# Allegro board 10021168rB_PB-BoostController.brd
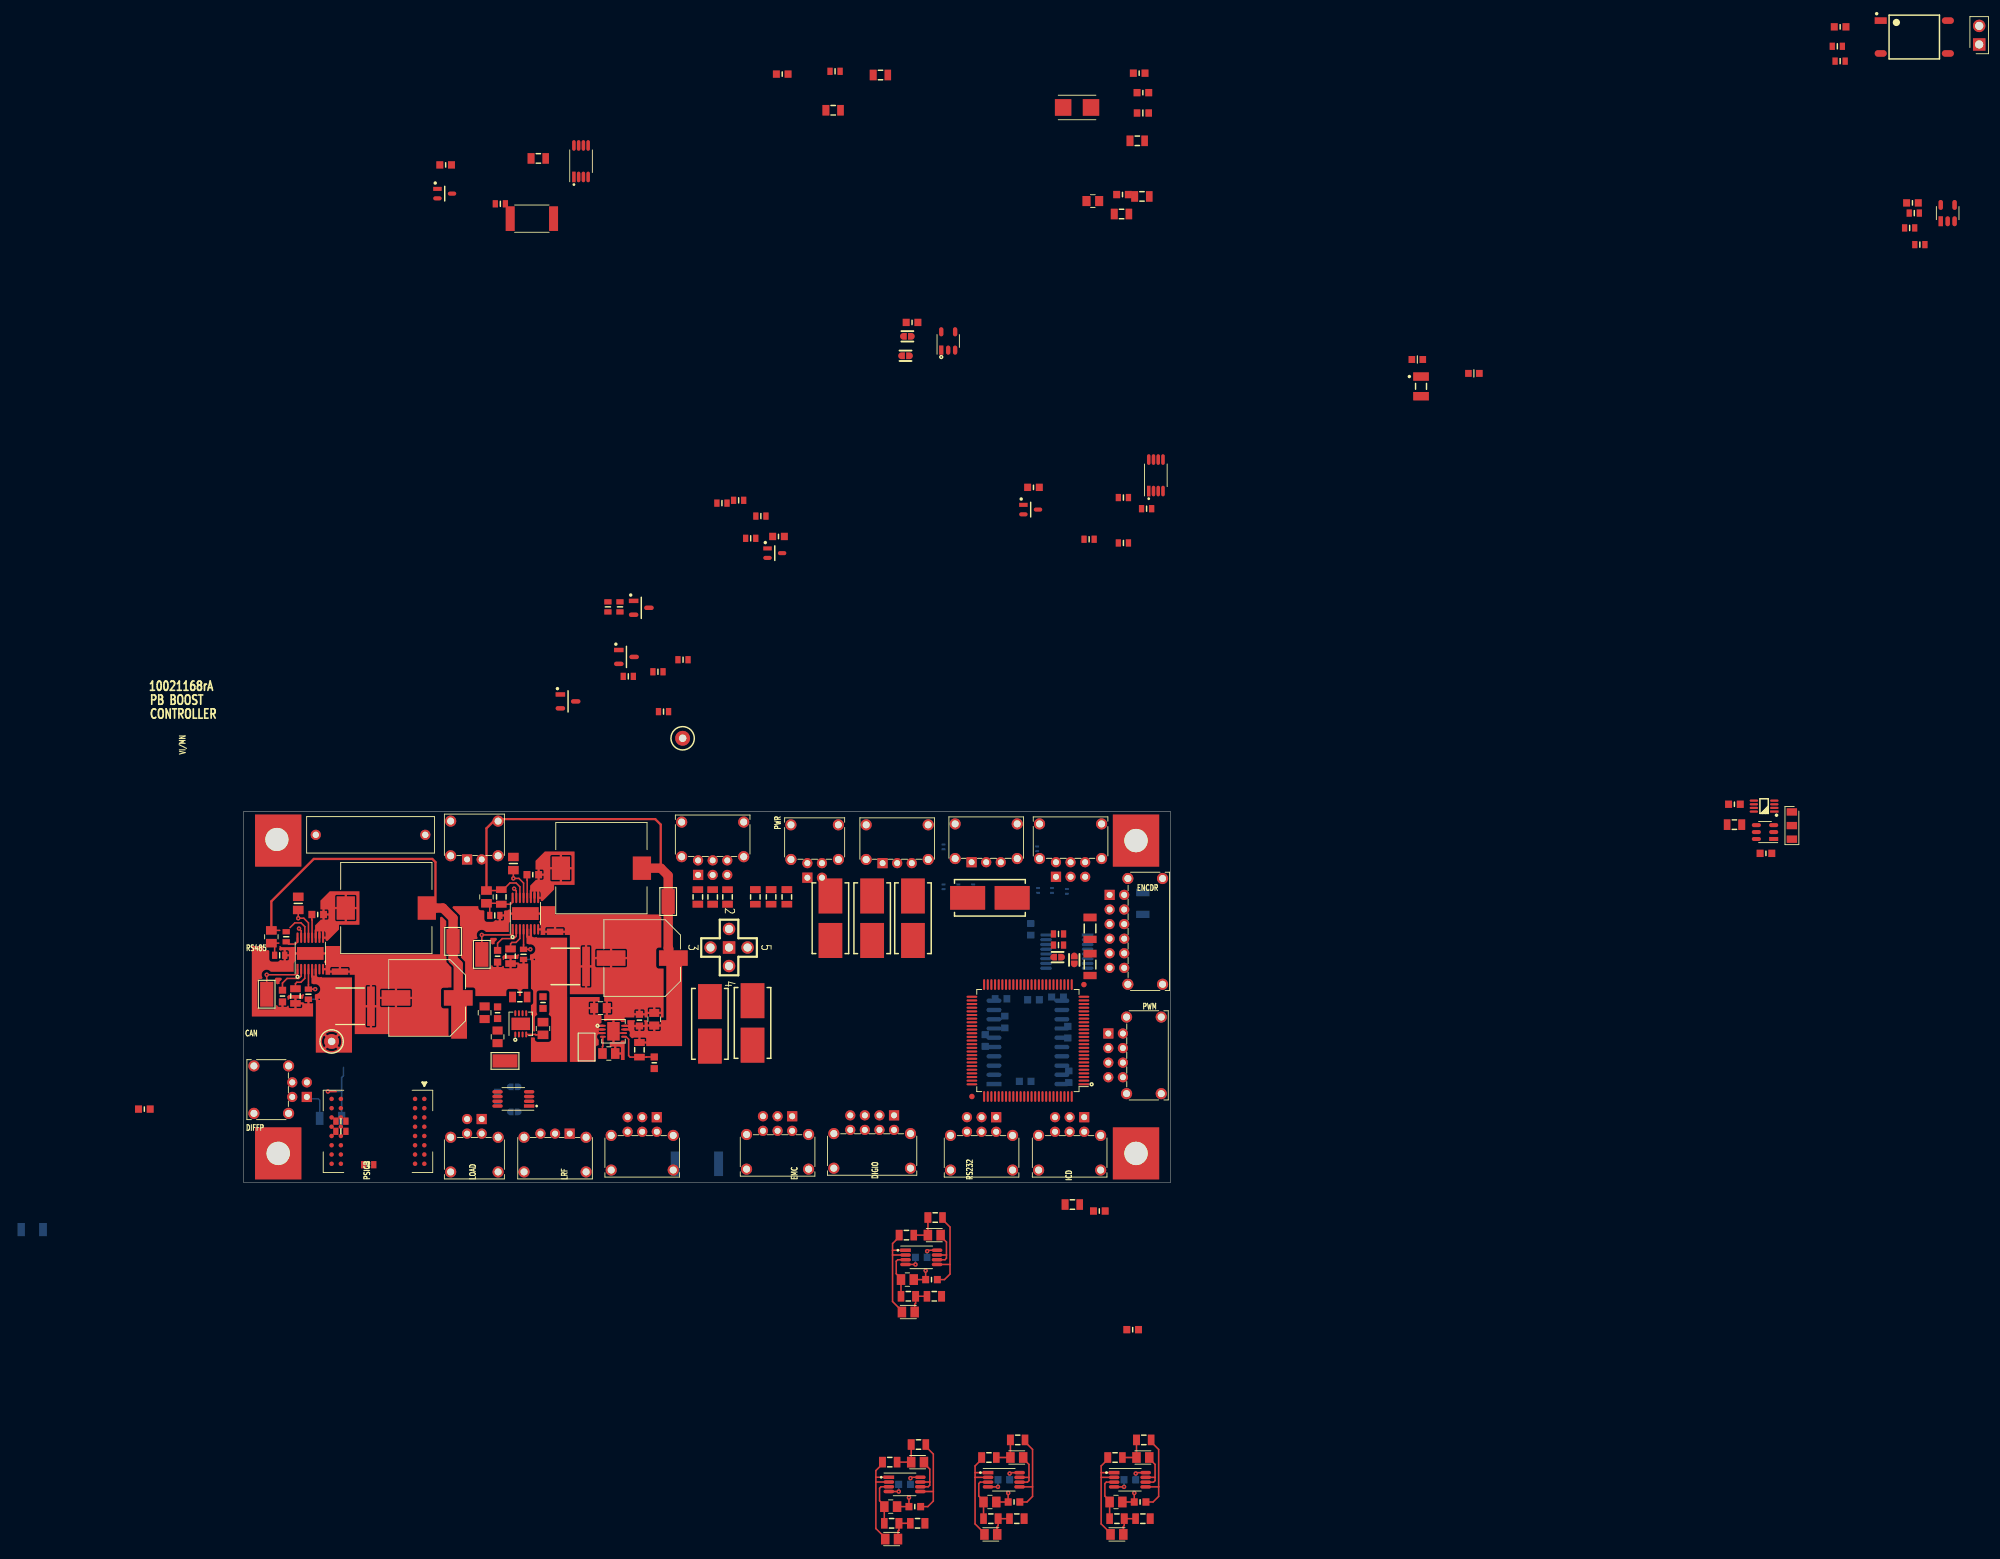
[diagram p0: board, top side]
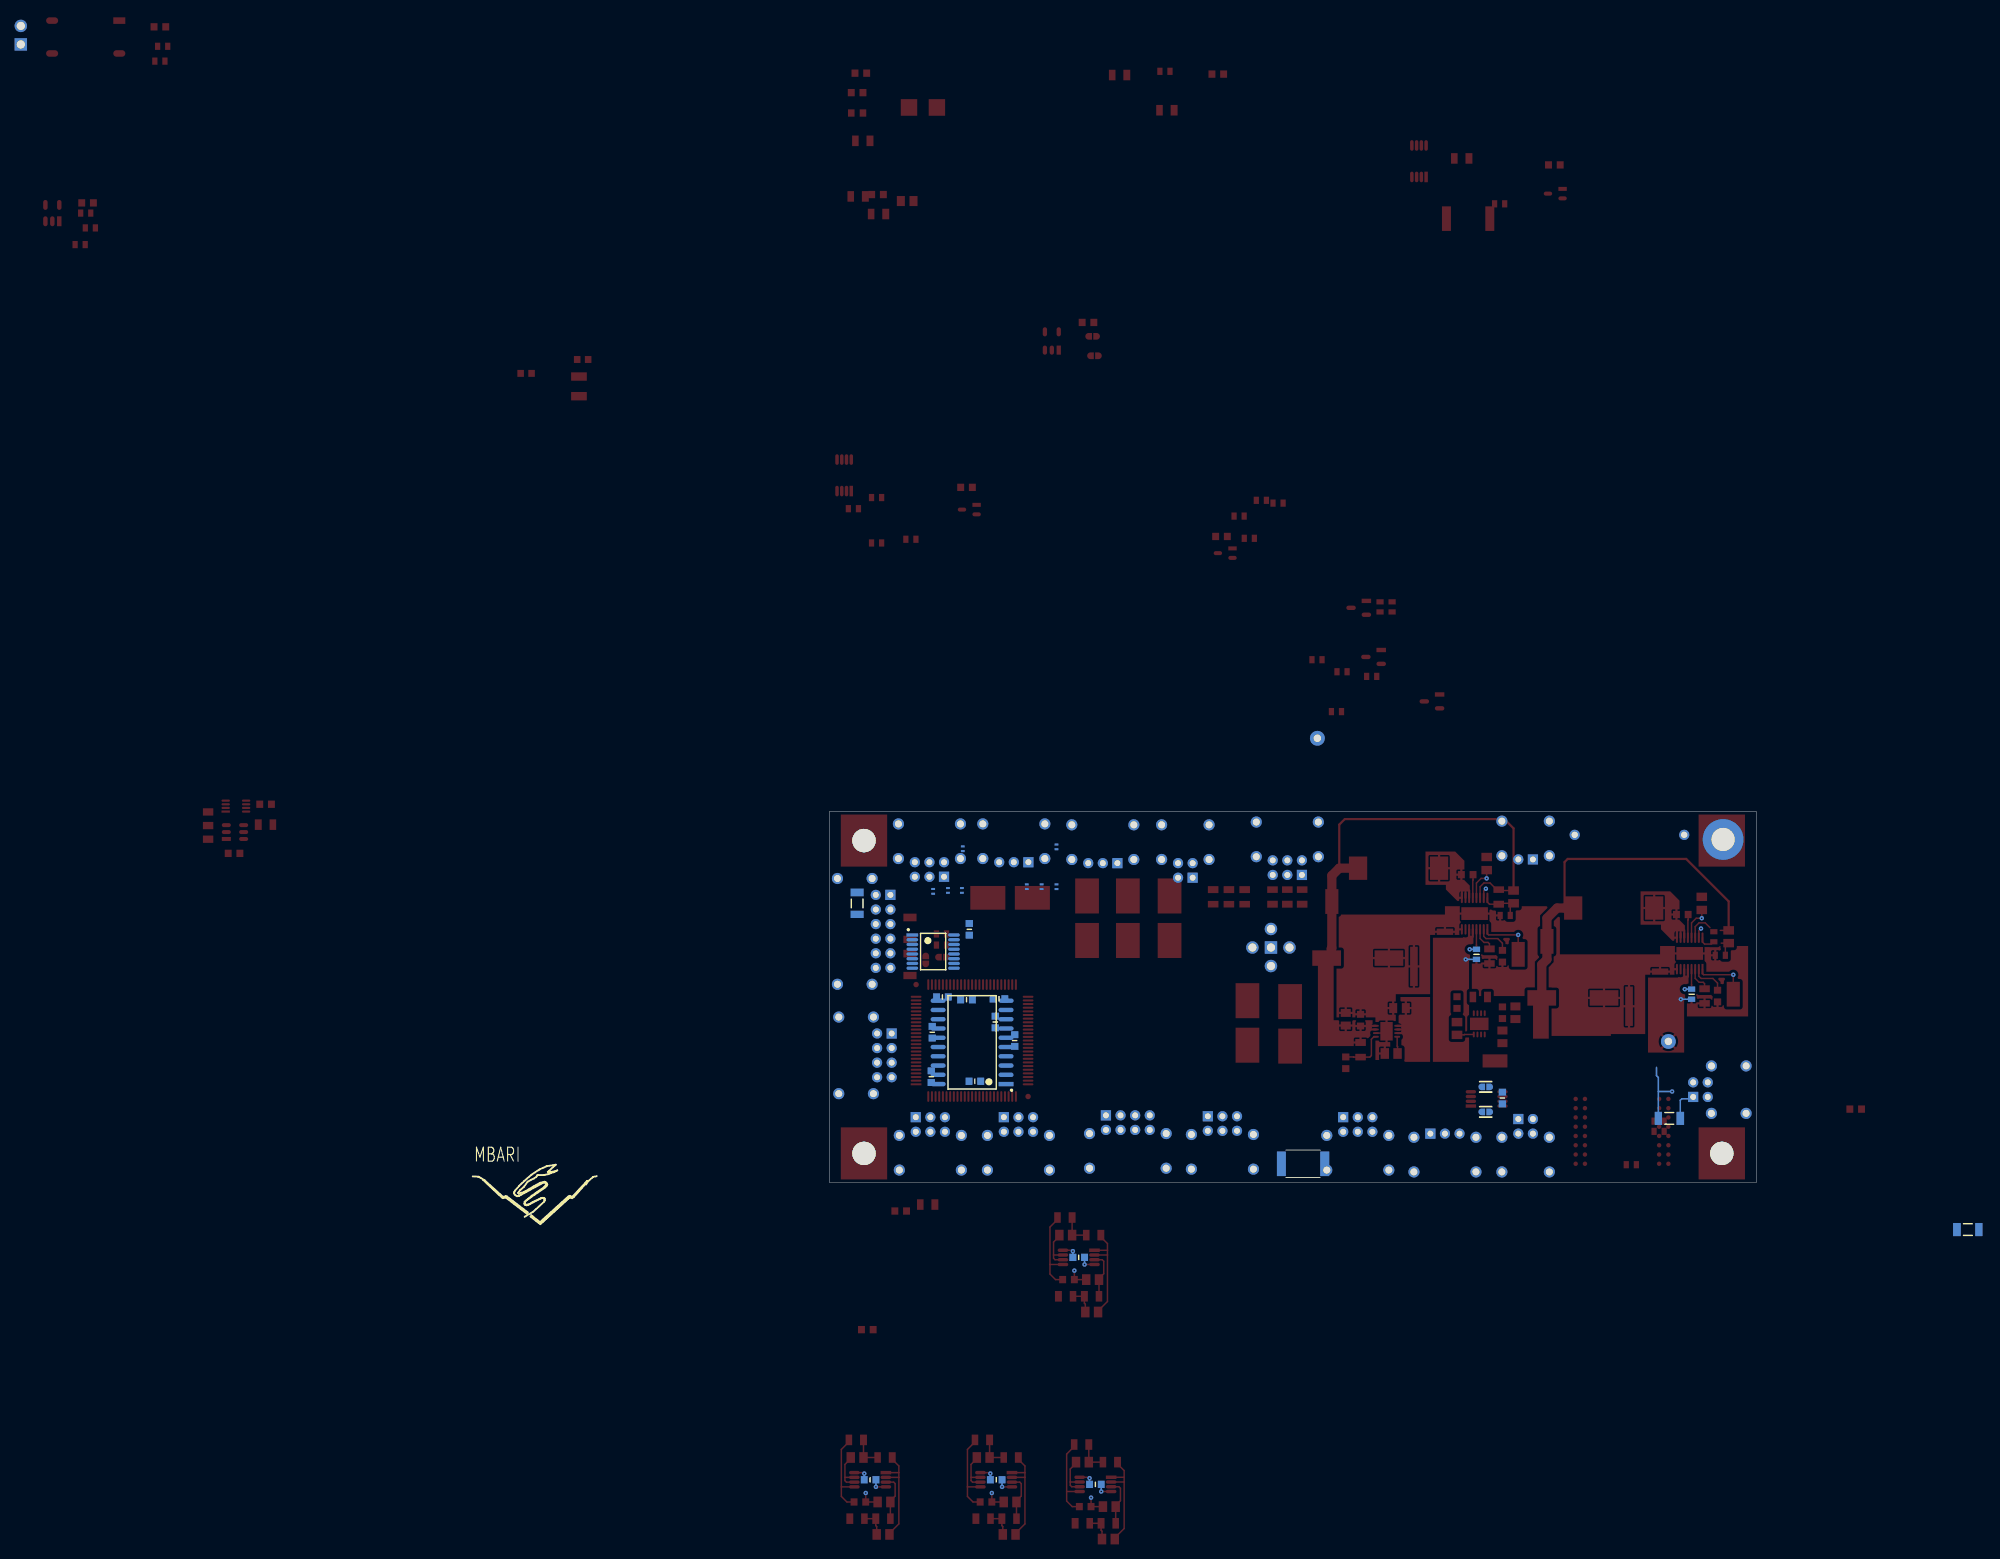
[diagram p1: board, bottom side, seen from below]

Outline 127 x 50.8 mm; copper layers: TOP, GND1, PWR, INR1, GND2, BOTTOM. Coordinates in mm from the lower left corner of the outline.
Outline path: 0,50.8 0,0 127,0 127,50.8 0,50.8

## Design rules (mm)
constraint set DEFAULT: min track width 0.203

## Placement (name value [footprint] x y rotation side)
C1  10uF  [CAPC2012X135N]  116.33 134.49 0 top
C2  0.10uF  [CAPC1608X87N]  120.4 135.38 0 top
C3  0.10uF  [CAPC1608X87N]  218.69 158.37 0 top
C4  22pF  [CAPC1608X90N_G100]  160.78 112.78 0 top
C5  22pF  [CAPC1608X90N_G100]  168.53 110.87 0 top
C6  33pF  [CAPC1608X90N]  122.68 152.02 0 top
C7  33pF  [CAPC1608X90N]  123.19 149.35 0 top
C8  0.10uF  [CAPC1608X87N]  103.76 25.15 180 bottom
C9  0.10uF  [CAPC1608X87N]  108.2 25.02 180 bottom
C10  0.10uF  [CAPC1608X87N]  111.51 25.4 180 bottom
C11  0.10uF  [CAPC1608X87N]  112.9 20.57 270 bottom
C12  0.10uF  [CAPC1608X87N]  113.03 14.48 270 bottom
C13  0.10uF  [CAPC1608X87N]  107.06 13.84 0 bottom
C14  0.10uF  [CAPC1608X87N]  101.6 19.43 270 bottom
C15  0.10uF  [CAPC1608X87N]  104.27 21.97 90 bottom
C39  0.10uF  [CAPC1608X87N]  117.22 -3.94 0 top
C40  0.10uF  [CAPC1608X87N]  34.8 11.56 90 bottom
C41  0.10uF  [CAPC1608X87N]  121.79 -20.19 0 top
C43  680pF  [CAPC2012X88N]  90.93 -13.34 0 top
C44  560pF  [CAPC1608X90N]  94.23 -13.34 180 top
C45  6800pF  [CAPC2012X90N]  91.06 -17.78 180 top
C46  6800pF  [CAPC2012X90N]  94.61 -7.24 0 top
C47  0.10uF  [CAPC1608X87N]  92.84 -10.29 180 bottom
C51  680pF  [CAPC2012X88N]  119.51 -43.81 0 top
C52  560pF  [CAPC1608X90N]  122.81 -43.81 180 top
C54  6800pF  [CAPC2012X90N]  119.63 -48.26 180 top
C55  6800pF  [CAPC2012X90N]  123.19 -37.72 0 top
C56  0.10uF  [CAPC1608X87N]  121.41 -40.77 180 bottom
C60  680pF  [CAPC2012X88N]  102.23 -43.81 0 top
C61  560pF  [CAPC1608X90N]  105.54 -43.81 180 top
C63  6800pF  [CAPC2012X90N]  102.36 -48.26 180 top
C64  6800pF  [CAPC2012X90N]  105.92 -37.72 0 top
C65  0.10uF  [CAPC1608X87N]  104.14 -40.77 180 bottom
C69  680pF  [CAPC2012X88N]  88.65 -44.45 0 top
C70  560pF  [CAPC1608X90N]  91.95 -44.45 180 top
C72  6800pF  [CAPC2012X90N]  88.77 -48.9 180 top
C73  6800pF  [CAPC2012X90N]  92.33 -38.35 0 top
C74  0.10uF  [CAPC1608X87N]  90.55 -41.4 180 bottom
C76  0.10uF  [CAPC1608X87N]  73.28 88.52 0 top
C77  0.10uF  [CAPC1608X87N]  108.2 95.25 0 top
C78  0.10uF  [CAPC1608X87N]  27.69 139.45 0 top
C79  0.10uF  [CAPC1608X87N]  73.79 151.89 0 top
C87  0.10uF  [CAPC1608X87N]  107.82 34.67 90 bottom
C88  0.10uF  [CAPC1608X87N]  228.6 134.24 0 top
C89  0.10uF  [CAPC1608X87N]  91.57 117.86 0 top
C90  0.10uF  [CAPC1608X87N]  -13.59 10.03 0 top
C91  BFC233860103  [CAPRR1500W60L1750T500H1100B]  17.4 47.62 0 top
C92  10.0pF  [CAPC2012X88N]  33.27 39.12 90 top
C93  1.0uF  [CAPC2012X140N]  36.96 43.69 90 top
C94  0.10uF  [CAPC1608X87N]  39.62 42.16 0 top
C95  0.10uF  [CAPC1608X87N]  34.8 30.99 270 top
C96  10uF  [CAPC5750X250N]  44.07 29.59 0 top
C97  0.10uF  [CAPC127X200X102L23N]  42.67 33.66 90 top
C98  10uF  [CAPC2012X135N]  56.26 22.35 90 top
C99  0.10uF  [CAPC1608X87N]  54.23 22.23 90 top
C100  2200uF  [CAPAE1030X1380DD450L320N]  54.61 30.73 180 top
C101  10uF  [CAPC2012X135N]  48.9 23.88 0 top
C102  0.10uF  [CAPC1608X87N]  56.26 16.38 270 top
C103  1000.0pF  [CAPC2012X88N]  50.04 17.65 0 top
C104  0.10uF  [CAPC1608X87N]  208.53 45.09 0 top
C105  0.10uF  [CAPC1608X87N]  204.22 51.82 180 top
C106  10.0pF  [CAPC2012X88N]  3.81 33.66 90 top
C107  1.0uF  [CAPC2012X140N]  7.49 38.23 90 top
C108  0.10uF  [CAPC1608X87N]  10.16 36.7 0 top
C109  0.10uF  [CAPC1608X87N]  5.33 25.53 270 top
C110  10uF  [CAPC5750X250N]  14.61 24.13 0 top
C111  0.10uF  [CAPC127X200X102L23N]  13.21 28.19 90 top
C112  10uF  [CAPC2012X135N]  33.02 23.24 270 top
C113  0.10uF  [CAPC1608X87N]  34.8 23.24 270 top
C114  2200uF  [CAPAE1030X1380DD450L320N]  25.15 25.27 180 top
C115  10uF  [CAPC2012X135N]  34.8 19.94 90 top
C116  0.10uF  [CAPC1608X87N]  41.02 24.64 270 top
C117  1000.0pF  [CAPC2012X88N]  41.02 21.08 90 top
D3  RCLAMP0531TQTCT  [DIONDFN2_100X60X43L25X50N]  108.84 40.01 90 bottom
D4  RCLAMP0531TQTCT  [DIONDFN2_100X60X43L25X50N]  110.74 40.01 90 bottom
D5  RCLAMP0531TQTCT  [DIONDFN2_100X60X43L25X50N]  112.78 39.88 90 bottom
D6  RCLAMP0531TQTCT  [DIONDFN2_100X60X43L25X50N]  108.71 45.72 270 bottom
D7  RCLAMP0531TQTCT  [DIONDFN2_100X60X43L25X50N]  95.89 40.51 90 bottom
D8  RCLAMP0531TQTCT  [DIONDFN2_100X60X43L25X50N]  97.92 40.51 90 bottom
D9  RCLAMP0531TQTCT  [DIONDFN2_100X60X43L25X50N]  99.95 40.51 90 bottom
D10  RCLAMP0531TQTCT  [DIONDFN2_100X60X43L25X50N]  95.89 45.97 270 bottom
DN1  BAT54SWT1G  [SOT65P220X100-3N_132]  27.56 135.51 0 top
DN9  BAT54SWT1G  [SOT65P220X100-3N_132]  107.82 92.2 0 top
DN10  BAT54SWT1G  [SOT65P220X100-3N_132]  72.77 86.23 0 top
F1  0154.125DR  [FUSM9750X381N]  91.69 36.2 270 top
F2  0154.125DR  [FUSM9750X381N]  86.11 36.2 270 top
F3  0154.125DR  [FUSM9750X381N]  80.39 36.2 270 top
F4  0154.125DR  [FUSM9750X381N]  69.72 21.84 90 top
F5  0154.125DR  [FUSM9750X381N]  102.23 38.99 180 top
F6  0154.125DR  [FUSM9750X381N]  63.88 21.72 90 top
J1  M80-8420242  [HARWIN_M80-8420242]  31.62 47.62 180 top
J2  M80-8510442  [HARWIN_M80-8510442]  3.3 12.7 270 top
J3  M80-8510642  [HARWIN_M80-8510642]  101.09 3.56 0 top
J4  M80-8510442  [HARWIN_M80-8510442]  31.62 3.3 0 top
J5  M80-8510642  [HARWIN_M80-8510642]  113.16 3.56 0 top
J6  M80-8510842  [HARWIN_M80-8510842]  86.11 3.81 0 top
J7  M80-8420342  [HARWIN_M80-8420342]  101.73 47.24 180 top
J8  M80-8420342  [HARWIN_M80-8420342]  89.53 47.12 180 top
J9  M80-8510442  [HARWIN_M80-8510442]  78.23 47.12 180 top
J10  M80-8510642  [HARWIN_M80-8510642]  54.61 3.56 0 top
J11  M80-8511242  [HARWIN_M80-8511242]  124 34.39 90 top
J12  M80-8510842  [HARWIN_M80-8510842]  123.83 17.4 90 top
J13  M80-8420342  [HARWIN_M80-8420342]  42.67 3.3 0 top
J14  M80-8510642  [HARWIN_M80-8510642]  64.26 47.5 180 top
J15  M80-8510642  [HARWIN_M80-8510642]  113.28 47.24 180 top
J16  M80-8510642  [HARWIN_M80-8510642]  73.15 3.68 0 top
JP1  LS=0.100"  [HDRV2W64P254_2X1_508X254H1363B]  237.74 155.96 90 top
JP2  QUAD JUMPER  [MISC_JMPR-SELECT-QUAD]  66.5 32.18 270 top
JR4  Low  [MISC_0805-3P-JMPR]  212.09 48.9 270 top
L3  220uH  [IND_NS-12]  49.02 43.05 0 top
L4  220uH  [IND_NS-12]  19.56 37.59 0 top
NOREF  -  []  0 0 90 top
NOREF#2  -  [unnamed#2]  122.25 3.96 0 top
NOREF#3  -  []  256.03 33.78 0 top
NOREF#4  -  []  0 0 0 top
NOREF#5  -  []  127 0 90 top
NOREF#6  -  [unnamed#2]  4.75 3.96 0 top
NOREF#7  -  []  0 0 0 top
NOREF#8  -  [unnamed#2]  122.25 46.84 0 top
NOREF#9  -  []  -50.8 -76.2 0 top
NOREF#10  -  []  0 0 0 top
NOREF#11  -  []  166.62 3.43 180 bottom
Q3  SI2308DS-T1-E3  [SOT95P237X112-3N_132]  44.45 65.91 0 top
Q4  SI2308DS-T1-E3  [SOT95P237X112-3N_132]  54.48 78.74 0 top
Q5  SI2308DS-T1-E3  [SOT95P237X112-3N_132]  52.45 72.01 0 top
R1  TBD  [RESC2012X50N]  123.06 135.13 0 top
R2  0.0  [RESC2012X50N]  120.27 132.72 0 top
R3  4.70K  [RESC1608X50N]  218.31 155.7 0 top
R4  1.00K  [RESC1608X50N]  218.69 153.67 0 top
R5  0.0  [RESC1609X55N]  123.19 146.56 0 top
R6  1.00M  [RESC2012X50N]  122.43 142.75 0 top
R24  100  [RESC2012X50N]  113.54 -3.05 0 top
R26  5.62K  [RESC2012X50N]  94.61 -15.62 180 top
R27  160.0K  [RESC2012X50N]  91.06 -15.62 180 top
R28  33.2K  [RESC2012X50N]  90.81 -7.24 0 top
R29  33.2K  [RESC2012X50N]  94.74 -4.83 0 top
R32  5.62K  [RESC2012X50N]  123.19 -46.1 180 top
R33  160.0K  [RESC2012X50N]  119.63 -46.1 180 top
R34  33.2K  [RESC2012X50N]  119.38 -37.72 0 top
R35  33.2K  [RESC2012X50N]  123.32 -35.31 0 top
R39  5.62K  [RESC2012X50N]  105.92 -46.1 180 top
R40  160.0K  [RESC2012X50N]  102.36 -46.1 180 top
R41  33.2K  [RESC2012X50N]  102.11 -37.72 0 top
R42  33.2K  [RESC2012X50N]  106.05 -35.31 0 top
R46  5.62K  [RESC2012X50N]  92.33 -46.74 180 top
R47  160.0K  [RESC2012X50N]  88.77 -46.74 180 top
R48  33.2K  [RESC2012X50N]  88.52 -38.35 0 top
R49  33.2K  [RESC2012X50N]  92.46 -35.94 0 top
R51  10.0K  [RESC1608X50N]  65.53 93.09 0 top
R52  16.2K  [RESC1608X50N]  67.82 93.47 0 top
R53  4.53K  [RESC1608X50N]  70.87 91.31 0 top
R54  10.0K  [RESC1608X50N]  115.82 88.14 0 top
R55  16.2K  [RESC1608X50N]  120.52 93.85 0 top
R56  4.53K  [RESC1608X50N]  120.52 87.63 0 top
R57  16.2K  [RESC1608X50N]  35.18 134.11 0 top
R58  150  [RESC6332X70N]  39.5 132.08 0 top
R59  0.0  [RESC2012X50N]  40.39 140.34 0 top
R60  16.2K  [RESC1608X50N]  81.03 152.27 0 top
R61  0.0  [RESC2012X50N]  80.77 146.94 0 top
R62  150  [RESC6332X70N]  62.1 2.54 180 bottom
R89  0.0  [RESC2012X50N]  87.25 151.76 0 top
R91  14.0K  [RESC1608X50N]  228.85 132.84 0 top
R92  14.0K  [RESC1608X50N]  228.22 130.81 0 top
R93  14.0K  [RESC1608X50N]  229.62 128.52 0 top
R94  60.4  [RESC3216X60N]  11.94 8.76 0 bottom
R95  60.4  [RESC3216X60N]  -28.96 -6.48 180 bottom
R96  0.0  [RESC1608X50N]  13.34 8.38 180 top
R97  TBD  [RESC1608X50N]  13.34 6.99 0 top
R98  TBD  [RESC1608X50N]  17.14 2.41 0 top
R99  TBD  [RESC1608X50N]  69.47 88.27 0 top
R100  TBD  [RESC1608X50N]  123.7 92.33 0 top
R101  165.0K  [RESC1608X50N]  52.7 69.34 0 top
R102  165.0K  [RESC1608X50N]  51.56 78.87 270 top
R103  165.0K  [RESC1608X50N]  56.77 69.98 0 top
R107  TBD  [RESC3216X60N]  115.95 34.8 270 top
R108  TBD  [RESC3216X60N]  115.95 29.84 270 top
R109  TBD  [RESC3216X60N]  123.19 38.23 270 bottom
R111  100  [RESC1608X50N]  57.53 64.52 0 top
R112  100  [RESC1608X50N]  49.91 78.87 270 top
R113  100  [RESC1608X50N]  60.2 71.63 0 top
R114  TBD  [RESC2012X50N]  62.23 39.12 90 top
R115  TBD  [RESC2012X50N]  64.26 39.12 90 top
R116  TBD  [RESC2012X50N]  66.29 39.12 90 top
R117  TBD  [RESC2012X50N]  74.42 39.12 270 top
R118  TBD  [RESC2012X50N]  72.26 39.12 270 top
R119  TBD  [RESC2012X50N]  70.1 39.12 270 top
R120  10.0K  [RESC1608X50N]  111.63 32.51 0 top
R121  10.0K  [RESC1608X50N]  111.63 34.04 0 top
R122  620.0K  [RESC2012X50N]  35.31 39.12 90 top
R123  243.0K  [RESC1608X50N]  34.42 36.58 0 top
R124  232.0K  [RESC2012X50N]  36.58 30.99 270 top
R125  20.0K  [RESC2012X50N]  54.23 18.16 270 top
R126  309.0K  [RESC1608X50N]  38.35 31.24 90 bottom
R127  619.0K  [RESC1608X50N]  38.35 31.24 270 top
R128  249.0K  [RESC2012X50N]  204.22 49.02 180 top
R129  866.0K  [RESC1608X50N]  5.84 33.66 90 top
R130  200.0K  [RESC1608X50N]  4.95 31.11 0 top
R131  232.0K  [RESC2012X50N]  7.11 25.53 270 top
R132  20.0K  [RESC2012X50N]  37.85 25.4 0 top
R133  309.0K  [RESC1608X50N]  8.89 25.78 90 bottom
R134  619.0K  [RESC1608X50N]  8.89 25.78 270 top
SB1  0603  [MISC_JUMPER_SM0603]  37.08 9.65 0 bottom
SB2  0603  [MISC_JUMPER_SM0603]  37.08 13.08 0 bottom
SB3  0603  [MISC_JUMPER_SM0603]  90.93 115.95 0 top
SB4  0603  [MISC_JUMPER_SM0603]  90.68 113.28 0 top
SB5  0603  [MISC_JUMPER_SM0603]  111.51 30.86 180 top
SB6  0603  [MISC_JUMPER_SM0603]  113.79 30.48 90 top
ST1  #4 SCREW TERMINAL  [MNT_C220H125]  4.57 46.99 0 top
SW1  FSM2JSMA  [SOIC450P1000X459R-4N]  228.85 156.97 0 top
TP1  RED  [TP_KEYSTONE_5000S_MINI]  12.06 19.3 270 top
TP2  BLACK  [TP_KEYSTONE_5000S_MINI]  60.15 60.86 0 top
TP5  5015  [TP_5015]  32.64 31.24 90 top
TP6  5015  [TP_5015]  58.17 38.48 270 top
TP7  5015  [TP_5015]  46.99 18.54 270 top
TP8  5015  [TP_5015]  3.17 25.78 90 top
TP9  5015  [TP_5015]  28.7 33.02 270 top
TP10  5015  [TP_5015]  35.81 16.64 0 top
U1  DSPIC33FJ256MC710A-H/PF  [QFP50P1600X1600X120-100L30N]  107.44 19.43 90 top
U2  REF1933AIDDCT  [SOT95P280X110-5L30N]  96.52 115.32 0 top
U8  AM26LS32ACPWR  [SOP65P640X120-16N]  112.78 31.62 180 bottom
U9  MAX3233EEWP+G36  [SOIC127P1032X265-20N]  107.44 19.18 0 bottom
U10  MAX3471EUA+  [SOP65P490X110-8L25N]  36.96 11.43 90 top
U11  24FC64FT-I/OT  [SOT23-5P95_270X145L35X35N]  233.43 132.84 0 top
U12  LTC2055HVHMS8#PBF  [SOP65P490X110-8L30N]  92.84 -10.29 270 top
U14  LTC2055HVHMS8#PBF  [SOP65P490X110-8L30N]  121.41 -40.77 270 top
U16  LTC2055HVHMS8#PBF  [SOP65P490X110-8L30N]  104.14 -40.77 270 top
U18  LTC2055HVHMS8#PBF  [SOP65P490X110-8L30N]  90.55 -41.4 270 top
U20  LTC2055HVHMS8#PBF  [SOP65P490X110-8L30N]  124.97 96.9 0 top
U21  LTC2055HVHMS8#PBF  [SOP65P490X110-8L30N]  46.23 139.95 0 top
U27  LTM2889IY-3#PBF  [LINEAR_BGA32]  18.41 6.99 180 top
U28  LT8610ABEMSE#PBF  [SOP50P490X110-17L30T175X364N]  38.61 36.83 0 top
U29  ADM7171ACPZ-3.3-R7  [SON50P300X300X80-9T170X254N]  50.67 20.7 270 top
U30  SN74AUP1G74DCUR  [SOP50P310X90-8N]  208.28 51.56 180 top
U31  LTC6906CS6#TRMPBF  [SOT95P280X100-6L20N]  208.41 48.01 90 top
U32  LT8610ABEMSE#PBF  [SOP50P490X110-17L30T175X364N]  9.14 31.37 0 top
U33  ADM7171ACPZ-5.0-R7  [SON50P300X300X80-9T170X254N]  37.97 21.72 0 top
Y1  32.768kHz  [OSCCC150X320X90-2N]  161.29 109.09 0 top
Y2  8MHz  [XTALSC500X500X135-2N]  114.17 147.32 0 top

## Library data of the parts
C1-C15 C39-C41 C43-C47 C51 C52 C54-C56 C60 C61 C63-C65 C69 C70 C72-C74 C76-C79 C87-C99 C101-C113 C115-C117 = CAP
C100 C114 = CAP_P
D3-D10 = DIODE_TVS_BI_DIR
DN1 DN9 DN10 = DIODE_DUAL_ACJ
F1-F6 = FUSEHOLDER_2T_2PIN
J1 = CON2
J2 J4 J9 = CON4
J3 J5 J10 J14-J16 = CON6
J6 J12 = CON8
J7 J8 J13 = CON3
J11 = CON12
JP1 = JUMPER_2PIN
JP2 = JUMPER_SELECT-QUAD
JR4 = RES_3PIN-JMPR
L3 L4 = IND_FERRITE
Q3-Q5 = MOSFET_I_EN_GSD
R1-R6 R24 R26-R29 R32-R35 R39-R42 R46-R49 R51-R62 R89 R91-R103 R107-R109 R111-R134 = RES
SB1-SB6 = SB_JUMPER
ST1 = SCREW-TERMINAL
SW1 = SW_SPST_12_34
TP1 TP2 TP5-TP10 = TESTPOINT
U1 = dsPIC33F_100TQFP
U2 = REF19xx
U8 = AM26LS32A_PW
U9 = MAX3233E
U10 = MAX3471xUA
U11 = 24FC64_OT
U12 U14 U16 U18 U20 U21 = LTC2055_MS8
U27 = LTM2889
U28 U32 = LT8610A
U29 U33 = ADM7171
U30 = 74xxx1G74DC-DLatch
U31 = LTC6906_S6
Y1 Y2 = CRYSTAL

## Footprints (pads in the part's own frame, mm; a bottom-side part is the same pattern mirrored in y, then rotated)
CAPAE1030X1380DD450L320N
  rect 3.94x2.121 smd: 1(-4.265,0) 2(4.265,0)
CAPC127X200X102L23N
  rect 0.861x2.261 smd: 1(-0.686,0) 2(0.686,0)
CAPC1608X87N
  rect 0.95x1.001 smd: 1(-0.8,0) 2(0.8,0)
CAPC1608X90N
  rect 0.95x1.001 smd: 1(-0.8,0) 2(0.8,0)
CAPC1608X90N_G100
  rect 0.899x0.95 smd: 1(-0.749,0) 2(0.749,0)
CAPC2012X88N
  rect 1.161x1.471 smd: 1(-0.874,0) 2(0.874,0)
CAPC2012X90N
  rect 1.161x1.471 smd: 1(-0.874,0) 2(0.874,0)
CAPC2012X135N
  rect 1.1x1.379 smd: 1(-0.866,0) 2(0.866,0)
CAPC2012X140N
  rect 1.151x1.45 smd: 1(-0.899,0) 2(0.899,0)
CAPC5750X250N
  rect 1.049x5.4 smd: 1(-2.85,0) 2(2.85,0)
CAPRR1500W60L1750T500H1100B
  round 1.397 hole 0.864: 1(-7.501,0) 2(7.501,0)
DIONDFN2_100X60X43L25X50N
  rect 0.279x0.521 smd: 1(-0.325,0) 2(0.325,0)
FUSM9750X381N
  rect 4.801x3.251 smd: 1(-3.051,0) 2(3.051,0)
HARWIN_M80-8420242
  round 1.524 hole 0.965: (-3.251,2.87) (-3.251,-1.88) (3.251,2.87) (3.251,-1.88)
  rect 1.397x1.397 hole 0.813: 1(1.001,3.371)
  round 1.397 hole 0.813: 2(-1.001,3.371)
HARWIN_M80-8420342
  round 1.524 hole 0.965: (-4.249,2.87) (-4.249,-1.88) (4.249,2.87) (4.249,-1.88)
  rect 1.397x1.397 hole 0.813: 1(1.999,3.371)
  round 1.397 hole 0.813: 2(0,3.371) 3(-1.999,3.371)
HARWIN_M80-8510442
  round 1.524 hole 0.965: (-3.251,2.87) (-3.251,-1.88) (3.251,2.87) (3.251,-1.88)
  rect 1.397x1.397 hole 0.813: 1(1.001,5.37)
  round 1.397 hole 0.813: 2(-1.001,5.37) 3(1.001,3.371) 4(-1.001,3.371)
HARWIN_M80-8510642
  round 1.524 hole 0.965: (-4.249,2.87) (-4.249,-1.88) (4.249,2.87) (4.249,-1.88)
  rect 1.397x1.397 hole 0.813: 1(1.999,5.37)
  round 1.397 hole 0.813: 2(0,5.37) 3(-1.999,5.37) 4(1.999,3.371) 5(0,3.371) 6(-1.999,3.371)
HARWIN_M80-8510842
  round 1.524 hole 0.965: (-5.25,2.87) (-5.25,-1.88) (5.25,2.87) (5.25,-1.88)
  rect 1.397x1.397 hole 0.813: 1(3,5.37)
  round 1.397 hole 0.813: 2(1.001,5.37) 3(-1.001,5.37) 4(-3,5.37) 5(3,3.371) 6(1.001,3.371) 7(-1.001,3.371) 8(-3,3.371)
HARWIN_M80-8511242
  round 1.524 hole 0.965: (-7.249,2.87) (-7.249,-1.88) (7.249,2.87) (7.249,-1.88)
  rect 1.397x1.397 hole 0.813: 1(5.001,5.37)
  round 1.397 hole 0.813: 2(3,5.37) 3(1.001,5.37) 4(-1.001,5.37) 5(-3,5.37) 6(-5.001,5.37) 7(5.001,3.371) 8(3,3.371) 9(1.001,3.371) 10(-1.001,3.371) 11(-3,3.371) 12(-5.001,3.371)
HDRV2W64P254_2X1_508X254H1363B
  rect 1.702x1.702 hole 1.118: 1(0,0)
  round 1.702 hole 1.118: 2(2.54,0)
IND_NS-12
  rect 2.499x3.2 smd: 1(-5.55,0) 2(5.55,0)
LINEAR_BGA32
  round 0.61 smd: A1(-6.35,-4.445) A2(-6.35,-3.175) A3(-6.35,-1.905) A4(-6.35,-0.635) A5(-6.35,0.635) A6(-6.35,1.905) A7(-6.35,3.175) A8(-6.35,4.445) B1(-5.08,-4.445) B2(-5.08,-3.175) B3(-5.08,-1.905) B4(-5.08,-0.635) B5(-5.08,0.635) B6(-5.08,1.905) B7(-5.08,3.175) B8(-5.08,4.445) K1(5.08,-4.445) K2(5.08,-3.175) K3(5.08,-1.905) K4(5.08,-0.635) K5(5.08,0.635) K6(5.08,1.905) K7(5.08,3.175) K8(5.08,4.445) L1(6.35,-4.445) L2(6.35,-3.175) L3(6.35,-1.905) L4(6.35,-0.635) L5(6.35,0.635) L6(6.35,1.905) L7(6.35,3.175) L8(6.35,4.445)
MISC_0805-3P-JMPR
  rect 1.001x1.42 smd: 1(-1.869,0) 2(0,0) 3(1.869,0)
MISC_JMPR-SELECT-QUAD
  rect 1.702x1.702 hole 1.118: 1(0,0)
  round 1.702 hole 1.118: 2(-2.54,0) 3(0,-2.54) 4(2.54,0) 5(0,2.54)
MISC_JUMPER_SM0603
  custom 0.227x0.227 smd: 1(-0.544,0) 2(0.544,0)
MNT_C220H125
  round 5.588 hole 3.175: 1(0,0)
OSCCC150X320X90-2N
  rect 2.149x1.151 smd: 1(0,1.349) 2(0,-1.349)
QFP50P1600X1600X120-100L30N
  round 0.749 smd: (-7.671,7.671) (7.671,-7.671)
  rect 0.279x1.471 smd: 1(-5.999,-7.671)
  oval 0.279x1.471 smd: 2(-5.499,-7.671) 3(-5.001,-7.671) 4(-4.501,-7.671) 5(-4,-7.671) 6(-3.5,-7.671) 7(-3,-7.671) 8(-2.499,-7.671) 9(-1.999,-7.671) 10(-1.501,-7.671) 11(-1.001,-7.671) 12(-0.5,-7.671) 13(0,-7.671) 14(0.5,-7.671) 15(1.001,-7.671) 16(1.501,-7.671) 17(1.999,-7.671) 18(2.499,-7.671) 19(3,-7.671) 20(3.5,-7.671) 21(4,-7.671) 22(4.501,-7.671) 23(5.001,-7.671) 24(5.499,-7.671) 25(5.999,-7.671) 51(5.999,7.671) 52(5.499,7.671) 53(5.001,7.671) 54(4.501,7.671) 55(4,7.671) 56(3.5,7.671) 57(3,7.671) 58(2.499,7.671) 59(1.999,7.671) 60(1.501,7.671) 61(1.001,7.671) 62(0.5,7.671) 63(0,7.671) 64(-0.5,7.671) 65(-1.001,7.671) 66(-1.501,7.671) 67(-1.999,7.671) 68(-2.499,7.671) 69(-3,7.671) 70(-3.5,7.671) 71(-4,7.671) 72(-4.501,7.671) 73(-5.001,7.671) 74(-5.499,7.671) 75(-5.999,7.671)
  oval 1.471x0.279 smd: 26(7.671,-5.999) 27(7.671,-5.499) 28(7.671,-5.001) 29(7.671,-4.501) 30(7.671,-4) 31(7.671,-3.5) 32(7.671,-3) 33(7.671,-2.499) 34(7.671,-1.999) 35(7.671,-1.501) 36(7.671,-1.001) 37(7.671,-0.5) 38(7.671,0) 39(7.671,0.5) 40(7.671,1.001) 41(7.671,1.501) 42(7.671,1.999) 43(7.671,2.499) 44(7.671,3) 45(7.671,3.5) 46(7.671,4) 47(7.671,4.501) 48(7.671,5.001) 49(7.671,5.499) 50(7.671,5.999) 76(-7.671,5.999) 77(-7.671,5.499) 78(-7.671,5.001) 79(-7.671,4.501) 80(-7.671,4) 81(-7.671,3.5) 82(-7.671,3) 83(-7.671,2.499) 84(-7.671,1.999) 85(-7.671,1.501) 86(-7.671,1.001) 87(-7.671,0.5) 88(-7.671,0) 89(-7.671,-0.5) 90(-7.671,-1.001) 91(-7.671,-1.501) 92(-7.671,-1.999) 93(-7.671,-2.499) 94(-7.671,-3) 95(-7.671,-3.5) 96(-7.671,-4) 97(-7.671,-4.501) 98(-7.671,-5.001) 99(-7.671,-5.499) 100(-7.671,-5.999)
RESC1608X50N
  rect 0.719x0.991 smd: 1(-0.691,0) 2(0.691,0)
RESC1609X55N
  rect 0.899x1.001 smd: 1(-0.8,0) 2(0.8,0)
RESC2012X50N
  rect 0.95x1.45 smd: 1(-1.001,0)
  rect 0.899x1.45 smd: 2(1.001,0)
RESC3216X60N
  rect 1.049x1.801 smd: 1(-1.501,0)
  rect 1.001x1.801 smd: 2(1.501,0)
RESC6332X70N
  rect 1.229x3.371 smd: 1(-2.969,0) 2(2.969,0)
SOIC127P1032X265-20N
  rect 2.05x0.599 smd: 1(-4.651,5.715)
  oval 2.05x0.599 smd: 2(-4.651,4.445) 3(-4.651,3.175) 4(-4.651,1.905) 5(-4.651,0.635) 6(-4.651,-0.635) 7(-4.651,-1.905) 8(-4.651,-3.175) 9(-4.651,-4.445) 10(-4.651,-5.715) 11(4.651,-5.715) 12(4.651,-4.445) 13(4.651,-3.175) 14(4.651,-1.905) 15(4.651,-0.635) 16(4.651,0.635) 17(4.651,1.905) 18(4.651,3.175) 19(4.651,4.445) 20(4.651,5.715)
SOIC450P1000X459R-4N
  rect 1.651x0.899 smd: 1(-4.6,2.25)
  oval 1.651x0.899 smd: 2(4.6,2.25) 3(4.6,-2.25) 4(-4.6,-2.25)
SON50P300X300X80-9T170X254N
  oval 0.269x0.81 smd: 1(-0.749,-1.455) 2(-0.249,-1.455) 3(0.249,-1.455) 4(0.749,-1.455) 5(0.749,1.455) 6(0.249,1.455) 7(-0.249,1.455) 8(-0.749,1.455)
  rect 2.54x1.699 smd: 9(0,0)
SOP50P310X90-8N
  rect 1.151x0.3 smd: 1(-1.4,0.749)
  oval 1.151x0.3 smd: 2(-1.4,0.249) 3(-1.4,-0.249) 4(-1.4,-0.749) 5(1.4,-0.749) 6(1.4,-0.249) 7(1.4,0.249) 8(1.4,0.749)
SOP50P490X110-17L30T175X364N
  rect 0.279x1.45 smd: 1(-1.75,-2.159)
  oval 0.279x1.45 smd: 2(-1.25,-2.159) 3(-0.749,-2.159) 4(-0.249,-2.159) 5(0.249,-2.159) 6(0.749,-2.159) 7(1.25,-2.159) 8(1.75,-2.159) 9(1.75,2.159) 10(1.25,2.159) 11(0.749,2.159) 12(0.249,2.159) 13(-0.249,2.159) 14(-0.749,2.159) 15(-1.25,2.159) 16(-1.75,2.159)
  rect 3.647x1.753 smd: 17(0,0)
SOP65P490X110-8L25N
  rect 0.47x1.42 smd: 1(-0.975,-2.164)
  oval 0.47x1.42 smd: 2(-0.325,-2.164) 3(0.325,-2.164) 4(0.975,-2.164) 5(0.975,2.164) 6(0.325,2.164) 7(-0.325,2.164) 8(-0.975,2.164)
SOP65P490X110-8L30N
  rect 0.48x1.45 smd: 1(-0.975,-2.159)
  oval 0.48x1.45 smd: 2(-0.325,-2.159) 3(0.325,-2.159) 4(0.975,-2.159) 5(0.975,2.159) 6(0.325,2.159) 7(-0.325,2.159) 8(-0.975,2.159)
SOP65P640X120-16N
  rect 1.6x0.45 smd: 1(-2.85,2.276)
  oval 1.6x0.45 smd: 2(-2.85,1.626) 3(-2.85,0.975) 4(-2.85,0.325) 5(-2.85,-0.325) 6(-2.85,-0.975) 7(-2.85,-1.626) 8(-2.85,-2.276) 9(2.85,-2.276) 10(2.85,-1.626) 11(2.85,-0.975) 12(2.85,-0.325) 13(2.85,0.325) 14(2.85,0.975) 15(2.85,1.626) 16(2.85,2.276)
SOT23-5P95_270X145L35X35N
  rect 0.61x1.359 smd: 1(-0.95,-1.12)
  oval 0.61x1.359 smd: 2(0,-1.12) 3(0.95,-1.12) 4(0.95,1.12) 5(-0.95,1.12)
SOT65P220X100-3N_132
  rect 1.151x0.551 smd: 1(-1.001,0.65)
  oval 1.151x0.551 smd: 2(-1.001,-0.65) 3(1.001,0)
SOT95P237X112-3N_132
  rect 1.3x0.599 smd: 1(-1.049,0.95)
  oval 1.3x0.599 smd: 2(-1.049,-0.95) 3(1.049,0)
SOT95P280X100-6L20N
  rect 0.551x1.24 smd: 1(-0.95,-1.186)
  oval 0.551x1.24 smd: 2(0,-1.186) 3(0.95,-1.186) 4(0.95,1.186) 5(0,1.186) 6(-0.95,1.186)
SOT95P280X110-5L30N
  rect 0.589x1.25 smd: 1(-0.95,-1.255)
  oval 0.589x1.25 smd: 2(0,-1.255) 3(0.95,-1.255) 4(0.95,1.255) 5(-0.95,1.255)
TP_5015
  rect 3.401x1.801 smd: 1(0,0)
TP_KEYSTONE_5000S_MINI
  round 2.032 hole 1.016: 1(0,0)
unnamed#2
  round 3.2 hole 3.2: (0,0)
XTALSC500X500X135-2N
  rect 2.25x2.281 smd: 1(-1.91,0) 2(1.91,0)

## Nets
3.3V: C8.1 C9.1 C10.1 C11.1 C12.1 C13.1 C14.1 C15.1 C39.1 C40.1 C41.1 C47.1 C56.1 C65.1 C74.1 C88.1 C90.1 C101.1 DN1.2 DN9.2 DN10.2 J3.2 J6.8 JP2.5 R1.1 R3.1 R5.1 R91.1 R92.1 R93.1 SB3.2 TP7.1(TP) U1.2 U1.16 U1.30 U1.37 U1.46 U1.62 U1.86 U2.3 U9.9 U9.10(\\F\O\R\C\E\O\F\F\) U10.8(VCC) U11.4 U12.8 U14.8 U16.8 U18.8 U20.8 U21.8 U27.A6 U27.A7 U27.A8 U27.B7 U27.B8 U29.1 U29.2(VOUT2) U29.3
5V: C87.1 C115.1 F5.2 JP2.4 SB4.2 SB6.1 TP10.1(TP) U8.16 U33.1 U33.2(VOUT2) U33.3
15V: C96.1 C97.1 C110.1 C111.1 F1.2 F2.2 F3.2 J1.1 J6.6 JP2.3 R126.1 R133.1 TP1.1(TP) U28.5 U28.6(VIN2) U32.5 U32.6(VIN2)
GND_EARTH: C91.1 ST1.1
GND_SIGNAL: C1.2 C2.2 C3.2 C4.2 C5.2 C6.2 C7.2 C8.2 C9.2 C10.2 C11.2 C12.2 C13.2 C14.2 C15.2 C39.2 C40.2 C41.2 C43.2 C44.2 C47.2 C51.2 C52.2 C56.2 C60.2 C61.2 C65.2 C69.2 C70.2 C74.2 C76.2 C77.2 C78.2 C79.2 C87.2 C88.2 C89.2 C90.2 C91.2 C93.2 C95.2 C96.2 C97.2 C98.2 C99.2 C100.2 C101.2 C102.2 C103.2 C104.2 C105.2 C107.2 C109.2 C110.2 C111.2 C112.2 C113.2 C114.2 C115.2 C116.2 C117.2 D3.1 D4.1 D5.1 D6.1 D7.1 D8.1 D9.1 D10.1 DN1.1 DN9.1 DN10.1 J1.2 J3.3 J4.4 J5.5 J6.5 J6.7 J7.3 J8.3 J9.4 J11.2 J12.8 J13.2 J15.5 J16.5 JR4.3 Q3.2(S) Q4.2(S) Q5.2(S) R53.1 R56.1 R59.2 R61.2 R89.2 R101.2 R102.2 R103.2 R120.2 R121.2 R123.2 R124.2 R127.2 R128.2 R130.2 R131.2 R134.2 SB5.1 SW1.1 SW1.2 TP2.1(TP) U1.15 U1.28 U1.31 U1.36 U1.45 U1.65 U1.75(VSS#75) U2.2 U8.8 U9.5 U9.18 U10.5 U11.2 U12.4(V-) U14.4(V-) U16.4(V-) U18.4(V-) U20.4(V-) U21.4(V-) U27.A1(\\R\E) U27.B1 U27.B2 U27.B3 U27.B4 U27.B5 U27.B6 U28.8 U28.17 U29.6 U29.9 U30.4 U31.2 U32.8 U32.17 U33.6 U33.9
AN0_LOADCELL: U1.25 U21.1 U21.2
AN1_POSITION: U1.24 U21.6 U21.7
AN10_DIFFPB: U1.34 U20.6 U20.7
AN11_TORQ_DIFFPA: U1.35 U20.1 U20.2
AN16_VSENSE: C46.2 U1.6 U12.6 U12.7
AN17_IBUS: C55.2 U1.7 U14.6 U14.7
AN18_ILOAD: C64.2 U1.8 U16.6 U16.7
AN19_IBOOST: C73.2 U1.9 U18.6 U18.7
ASIG_IBOOST_3V: J6.4 R46.1
ASIG_IBUS_3V: J6.2 R32.1
ASIG_ILOAD_3V: J6.3 R39.1
ASIG_VBUS_3V: J6.1 R26.1
CAN1_RX: U1.87 U27.A2
CAN1_TX: U1.88 U27.A3
CANGND: J2.3 R96.2 R97.1 R98.2 U27.K1 U27.K2 U27.K3 U27.K4 U27.K6 U27.K7 U27.K8 U27.L4
CANH: J2.1 R94.1 U27.L3
CANL: J2.2 R95.2 U27.L1
D1+: J14.1 R114.2
D1-: J14.4 R117.1
D2+: J14.2 R115.2
D2-: J14.5 R118.1
D3+: J14.3 R116.2
D3-: J14.6 R119.1
EEPROM_WP: R93.2 U1.58 U11.5(WP)
ENC_A_A: J11.3 R107.1 U8.2
ENC_A_B: J11.4 R107.2 U8.1
ENC_B_A: J11.5 R108.1 U8.6
ENC_B_B: J11.6 R108.2 U8.7
ENC_Z_A: J11.7 R109.1 U8.10
ENC_Z_B: J11.8 R109.2 U8.9
HALL_U: J11.11
HALL_V: J11.10
HALL_W: J11.9
I2C1_SCL: R91.2 U1.57 U11.1
I2C1_SDA: R92.2 U1.56 U11.3
LASERRNGPWR_15V_INPUT: J10.6
LASERRNGPWR_15V_SWITCHED: F4.2
MCLR: R4.2 R24.1 U1.13
OSC1: C6.1 R5.2 R6.2 U1.63 Y2.1
OSC2: C7.1 R6.1 U1.64 Y2.2
PHASEA: TP5.1(TP) U28.1 U30.2 U30.3
PHASEB: TP8.1(TP) U30.5 U32.1
PSIGA_10V: J7.2 R51.1
PSIGB_10V: J8.2 R54.1
PWM1H: J12.1 U1.94
PWM1L: J12.2 U1.93
PWM2H: J12.3 U1.99
PWM2L: J12.4 U1.98
PWM3H: J12.5 U1.3
PWM3L: J12.6 U1.100
PWM4L: J12.7 U1.4
RB3_ENC_Z: U1.22 U8.11
RB4_ENC_A: U1.21 U8.3
RB5_ENC_B: U1.20 U8.5
RB6_PGEC1: J3.5 U1.26
RB7_PGED1: J3.4 U1.27
RD1-5VPG: U1.76
RD2_GASBYPASS_EN: R112.2 U1.77
RD3_STEPPER_ENABLE: R111.2 U1.78
RD4_HALL_W: U1.81
RD5_HALL_V: U1.82
RD6_HALL_U: U1.83
RD7_AUX: R113.2 U1.84
RD12_LRF_EN: U1.79
RD13_NFAULT_LRFPOW: U1.80
RF12: U1.40 U10.2
RF13: U1.39 U10.3
RG0_CAN1_SILENT: U1.90 U27.A4
RG1_CAN1_ENABLE: U1.89 U27.A5
RG14_SW1_NFLT: U1.95
RG15_SW1_EN: U1.1
RS232_CTS: J5.4 U9.20
RS232_RTS: J5.2 U9.19
RS232_RXD: J5.3 U9.8
RS232_TXD: J5.1 U9.7
RS485_A: J4.2 SB2.1 U10.6
RS485_B: J4.1 SB1.1 U10.7
SOSCI: C5.1 U1.73 Y1.2
SOSCO: C4.1 U1.74 Y1.1
SPI1_MISO: D9.2(A2) J16.3 U1.54
SPI1_MOSI: D8.2(A2) J16.2 U1.53
SPI1_SCLK: D7.2(A2) J16.1 U1.55
SPI1_SS: D10.2(A2) J16.4 U1.23
SPI2_MISO: D5.2(A2) J15.3 U1.11
SPI2_MOSI: D4.2(A2) J15.2 U1.12
SPI2_SCLK: D3.2(A2) J15.1 U1.10
SPI2_SS: D6.2(A2) J15.4 U1.14
SW1_INPUT: J13.3
U1CTS: U1.47 U9.1
U1RTS: U1.48 U9.3
U1RXD: U1.52 U9.6
U1TXD: U1.51 U9.4
U2RXD: SB1.2 U1.49 U10.1
U2TXD: SB2.2 U1.50 U10.4
N08765: C1.1 C2.1 R1.2 R2.2
N08773: R2.1 U1.85
N14987: JP1.1 R3.2 R4.1 SW1.3 SW1.4
N25385: F5.1 J11.1
N38405: C3.1 JP1.2
N39747: U1.29 U2.5(VREF)
N47726: J3.1 R24.2
N72482: C77.1 DN9.3(J) R55.2 U20.5
N72600: R51.2 R52.1 R53.2 R99.2
N72690: C76.1 DN10.3(J) R52.2 U20.3
N72804: R54.2 R55.1 R56.2 R100.2
N72852: F2.1 J8.1 R100.1
N75830: F1.1 J7.1 R99.1
N76571: F3.1 J9.1
N76619: J9.2 R57.2 R58.1
N76675: J9.3 R58.2 R59.1
N76787: C78.1 DN1.3(J) R57.1 U21.3
N77226: F4.1 J10.1
N77274: J10.2 R60.2 R62.1
N77330: J10.3 R61.1 R62.2
N77442: C79.1 R60.1 U21.5
N78880: C45.2 R28.1 U12.1 U12.2
N79426: C45.1 R26.2 R27.1
N79442: C43.1 R27.2 U12.3
N79600: C46.1 R28.2 R29.1
N79616: C44.1 R29.2 U12.5
N83438: C54.2 R34.1 U14.1 U14.2
N83538: C54.1 R32.2 R33.1
N83554: C51.1 R33.2 U14.3
N83666: C55.1 R34.2 R35.1
N83682: C52.1 R35.2 U14.5
N84265: C63.2 R41.1 U16.1 U16.2
N84365: C63.1 R39.2 R40.1
N84381: C60.1 R40.2 U16.3
N84493: C64.1 R41.2 R42.1
N84509: C61.1 R42.2 U16.5
N85113: C72.2 R48.1 U18.1 U18.2
N85213: C72.1 R46.2 R47.1
N85229: C69.1 R47.2 U18.3
N85341: C73.1 R48.2 R49.1
N85357: C70.1 R49.2 U18.5
N140572: F6.2
N168303: C89.1 SB3.1 SB4.1 U2.4
N249678: J10.4 J10.5 R89.1
N306497: F6.1 J13.1
N326336: R94.2 R95.1 U27.L2
N326647: R96.1 U27.L5
N327074: R98.1 U27.L7 U27.L8
N327081: R97.2 U27.L6
N348444: Q4.1 R102.1 R112.1
N352220: Q3.1 R101.1 R111.1
N352274: Q5.1 R103.1 R113.1
N352849: Q3.3 R117.2
N352881: Q4.3 R118.2
N352913: Q5.3 R119.2
N363907: SB6.2 U8.4
N363963: SB5.2 U8.12(\\G)
N375304: JP2.1 R114.1 R115.1 R116.1
N393608: R120.1 U8.14
N393691: R121.1 U8.15
N1673905: C93.1 C104.1 C105.1 JR4.1 U28.13 U30.6 U30.7 U30.8(VCC) U31.6(V+)
N1674043: C92.1 R122.1 R123.1 U28.16
N1674071: C92.2 C98.1 C99.1 C100.1 L3.2 R122.2 R125.1 TP6.1(TP) U28.14 U29.7 U29.8
N1674311: C94.2 L3.1 U28.9 U28.10 U28.11
N1674335: C94.1 U28.12
N1674457: R124.1 U28.3
N1674471: C95.1 U28.2
N1674839: C103.1 U29.4
N1674895: C102.1 R125.2 U28.15 U29.5
N1674997: R126.2 R127.1 U28.4
N1675145: U30.1 U31.1
N1675163: R128.1 U31.4
N1675171: U31.5
N1675229: JR4.2 U31.3
N1676791: C106.2 C112.1 C113.1 C114.1 L4.2 R129.2 R132.1 TP9.1(TP) U32.14 U33.7 U33.8
N1677013: C117.1 U33.4
N1677049: C116.1 R132.2 U32.15 U33.5
N1677171: R133.2 R134.1 U32.4
N1677399: C106.1 R129.1 R130.1 U32.16
N1677783: C108.2 L4.1 U32.9 U32.10 U32.11
N1677807: C108.1 U32.12
N1677819: C107.1 U32.13
N1677947: R131.1 U32.3
N1677961: C109.1 U32.2

Pads without a net: J2 4; J3 6; J4 3; J5 6; J11 12; J15 6; J16 6; JP2 2; U1 5 17 18 19 32 33 38 41 42 43 44 59 60 61 66 67 68 69 70 71 72 91 92 96 97; U2 1; U8 13; U9 2 11 12 13 14 15 16 17; U27 K5; U28 7; U32 7

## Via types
v1: diameter 0.61, hole 0.254, TOP to BOTTOM, 23 vias

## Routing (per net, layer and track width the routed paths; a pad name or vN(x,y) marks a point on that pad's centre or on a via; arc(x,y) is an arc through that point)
3.3V: length 14
  TOP w0.203: v1(104.94,-39.92) 105.06,-39.79 U16.8 ; v1(93.64,-9.44) 93.76,-9.31 U12.8 ; v1(91.35,-40.55) 91.48,-40.43 U18.8 ; U14.8 122.34,-39.79 v1(122.21,-39.92)
  TOP w0.305: C101.1 48.03,24.86 ; C101.1 48.03,22.89 ; C101.1 47.18,23.88 ; 48.52,20.45 U29.3 ; 48.52,21.45 U29.1 ; 48.52,20.95 U29.2
  BOTTOM w0.203: C47.1 v1(93.64,-9.44) ; C65.1 v1(104.94,-39.92) ; C56.1 v1(122.21,-39.92) ; C74.1 v1(91.35,-40.55)
15V: length 13.2
  TOP w0.305: 39.36,33.65 U28.6 ; 10.98,20.39 TP1.1 ; TP1.1 13.15,20.39 ; TP1.1 10.98,18.22 ; TP1.1 13.15,18.22 ; 38.86,33.65 U28.5 ; 9.39,28.19 U32.5 ; 9.89,28.19 U32.6
  BOTTOM w0.203: R133.1 v1(10.36,25.09) ; R126.1 v1(39.82,30.55)
GND_SIGNAL: length 93.2
  TOP w0.203: U14.4 120.61,-41.74 v1(120.61,-41.74) ; v1(93.43,-12.1) C44.2 C43.2 ; U18.4 89.75,-42.38 v1(89.75,-42.38) ; U12.4 92.03,-11.26 v1(92.04,-11.26) ; v1(122.01,-42.58) C52.2 C51.2 ; v1(103.34,-41.74) 103.34,-41.74 U16.4 ; v1(104.74,-42.58) C61.2 C60.2 ; v1(91.15,-43.22) C70.2 C69.2 ; U29.6 50.92,20.45 U29.9
  TOP w0.305: 50.91,18.68 C103.2 51.79,17.65 ; C114.2 23.15,25.27 ; C114.2 20.88,26.63 ; C114.2 20.88,23.92 ; C114.2 18.62,25.27 ; 40.73,36.83 U28.17 36.49,36.83 ; 41.25,34.34 C97.2 ; C97.2 44.1,34.34 ; C97.2 42.67,35.07 ; 50.67,22.27 U29.9 50.67,19.14 ; C99.2 54.23,23.79 ; C99.2 55.02,23.03 ; C99.2 53.43,23.03 ; C110.2 18.28,24.13 ; C110.2 17.45,21.14 ; C110.2 17.45,27.12 ; C110.2 16.63,24.13 ; 8.89,24.43 R134.2 ; R131.2 7.11,25.27 ; R131.2 8.13,24.53 ; R131.2 7.11,23.78 ; 11.78,28.88 C111.2 ; C111.2 13.21,29.61 ; C111.2 14.63,28.88 ; C101.2 49.76,24.86 ; C101.2 49.76,22.89 ; C101.2 50.61,23.88 ; C98.2 56.26,24.06 ; C98.2 55.28,23.22 ; C98.2 57.25,23.22 ; 46.1,29.59 C96.2 ; C96.2 46.92,26.6 ; C96.2 47.74,29.59 ; C96.2 46.92,32.59 ; R124.2 36.58,30.73 ; R124.2 37.6,29.99 ; R124.2 36.58,29.24 ; 34.8,29.42 C95.2 ; 35.11,35.79 R123.2 35.76,36.58 ; 38.35,29.9 R127.2 ; U32.8 11.33,29.21 ; 7.03,31.37 U32.17 11.26,31.37 ; 48.08,30.73 C100.2 ; C100.2 50.35,29.38 ; C100.2 52.61,30.73 ; C100.2 50.35,32.09 ; U28.8 40.79,34.67 ; 5.64,30.33 R130.2 ; R130.2 6.3,31.11 ; R130.2 5.64,31.9 ; 5.33,23.96 C109.2
  BOTTOM w0.203: C47.2 v1(92.04,-11.26) ; C65.2 v1(103.34,-41.74) ; C74.2 v1(89.75,-42.38) ; C56.2 v1(120.61,-41.74)
AN16_VSENSE: length 6.2
  TOP w0.203: C46.2 95.49,-7.39 96.28,-8.19 96.28,-9.96 ; 96.28,-9.96 96.28,-10.41 96.08,-10.61 U12.6 ; 96.28,-9.96 U12.7
AN17_IBUS: length 6.2
  TOP w0.203: 124.86,-40.44 124.86,-40.89 124.66,-41.09 U14.6 ; 124.86,-40.44 U14.7 ; 124.86,-40.44 124.86,-38.67 124.06,-37.87 C55.2
AN18_ILOAD: length 6.2
  TOP w0.203: U16.6 107.38,-41.09 107.59,-40.89 107.59,-40.44 ; C64.2 106.79,-37.87 107.59,-38.67 107.59,-40.44 ; 107.59,-40.44 U16.7
AN19_IBOOST: length 6.2
  TOP w0.203: 94,-41.08 U18.7 ; 94,-41.08 94,-41.52 93.79,-41.73 U18.6 ; 94,-41.08 94,-39.3 93.2,-38.51 C73.2
CANH: length 3.8
  BOTTOM w0.203: 9.18,11.45 10.23,11.45 10.44,11.24 R94.1
PHASEA: length 7.6
  TOP w0.203: TP5.1 v1(32.64,33.91) 36.7,33.91 36.86,34.06 U28.1
PHASEB: length 7.6
  TOP w0.203: U32.1 7.39,28.6 7.24,28.45 v1(3.17,28.45) TP8.1
N78880: length 15
  TOP w0.203: R28.1 89.8,-7.49 88.9,-8.39 88.9,-9.31 ; 88.9,-9.31 U12.1 ; 88.9,-9.31 88.9,-9.96 ; C45.2 90.19,-17.63 88.9,-16.34 88.9,-9.96 ; 88.9,-9.96 U12.2
N79426: length 3.8
  TOP w0.203: C45.1 91.93,-16.7 92.06,-16.58 R27.1 R26.2
N79442: length 6.4
  TOP w0.203: U12.3 89.61,-10.61 89.41,-10.82 89.41,-12.53 90.06,-13.18 C43.1 R27.2
N79600: length 4.3
  TOP w0.203: R28.2 C46.1 R29.1
N79616: length 12
  TOP w0.203: R29.2 95.74,-5.1 96.77,-6.13 96.77,-11.26 ; 96.77,-11.26 U12.5 ; 96.77,-11.26 96.77,-12.57 96.01,-13.34 C44.1
N83438: length 15
  TOP w0.203: 117.47,-39.79 U14.1 ; 117.47,-39.79 117.47,-38.87 118.38,-37.97 R34.1 ; 117.47,-39.79 117.47,-40.44 ; 117.47,-40.44 117.47,-46.82 118.76,-48.11 C54.2 ; 117.47,-40.44 U14.2
N83538: length 3.8
  TOP w0.203: R32.2 R33.1 120.63,-47.06 120.51,-47.18 C54.1
N83554: length 6.4
  TOP w0.203: R33.2 C51.1 118.63,-43.66 117.98,-43.01 117.98,-41.3 118.19,-41.09 U14.3
N83666: length 4.3
  TOP w0.203: R34.2 C55.1 R35.1
N83682: length 12
  TOP w0.203: 125.35,-41.74 125.35,-36.61 124.32,-35.58 R35.2 ; 125.35,-41.74 125.35,-43.05 124.59,-43.81 C52.1 ; 125.35,-41.74 U14.5
N84265: length 15
  TOP w0.203: C63.2 101.49,-48.11 100.2,-46.82 100.2,-40.44 ; 100.2,-39.79 100.2,-40.44 ; 100.2,-39.79 U16.1 ; 100.2,-39.79 100.2,-38.87 101.11,-37.97 R41.1 ; 100.2,-40.44 U16.2
N84365: length 3.8
  TOP w0.203: C63.1 103.24,-47.18 103.36,-47.06 R40.1 R39.2
N84381: length 6.4
  TOP w0.203: R40.2 C60.1 101.36,-43.66 100.71,-43.01 100.71,-41.3 100.91,-41.09 U16.3
N84493: length 4.3
  TOP w0.203: R42.1 C64.1 R41.2
N84509: length 12
  TOP w0.203: 108.08,-41.74 U16.5 ; 108.08,-41.74 108.08,-36.61 107.05,-35.58 R42.2 ; 108.08,-41.74 108.08,-43.05 107.31,-43.81 C61.1
N85113: length 15
  TOP w0.203: 86.61,-40.43 86.61,-41.08 ; 86.61,-40.43 U18.1 ; 86.61,-40.43 86.61,-39.51 87.52,-38.61 R48.1 ; 86.61,-41.08 86.61,-47.45 87.9,-48.74 C72.2 ; 86.61,-41.08 U18.2
N85213: length 3.8
  TOP w0.203: R46.2 R47.1 89.77,-47.69 89.65,-47.82 C72.1
N85229: length 6.4
  TOP w0.203: U18.3 87.33,-41.73 87.12,-41.93 87.12,-43.64 87.77,-44.3 C69.1 R47.2
N85341: length 4.3
  TOP w0.203: R49.1 C73.1 R48.2
N85357: length 12
  TOP w0.203: C70.1 93.73,-44.45 94.49,-43.69 94.49,-42.38 ; R49.2 93.46,-36.22 94.49,-37.25 94.49,-42.38 ; 94.49,-42.38 U18.5
N326336: length 10.1
  TOP w0.203: v1(11.56,12.45) 12.7,12.45
  BOTTOM w0.203: 13.69,15.75 13.69,14.62 13.44,14.36 13.44,12.45 ; R94.2 13.44,12.45 ; 13.44,12.45 v1(11.56,12.45)
N1673905: length 4.8
  TOP w0.203: C93.1 v1(36.96,41.66) 37.72,41.66 38.36,41.02 U28.13
N1674043: length 6.1
  TOP w0.203: U28.16 36.86,38.4 36.57,38.12 R122.1 35.18,38.24 33.52,38.24 ; 33.52,38.24 C92.1 ; 33.52,38.24 33.73,38.04 R123.1
N1674071: length 69.7
  TOP w0.203: U28.14 37.86,40.5 37.34,41.02 36.49,41.02 35.58,40.12 R122.2 35.18,39.99 C92.2
  TOP w0.305: 55.25,19.16 R125.1 54.23,19.93 ; 56.26,20.64 C98.1 ; C98.1 55.28,21.49 ; C98.1 57.25,21.49 ; 54.23,20.66 C99.1 ; C99.1 55.02,21.42 ; C99.1 53.43,21.42 ; U29.8 52.83,21.45 ; C92.2 33.27,48.51 34.54,49.78 56.39,49.78 57.15,49.02 57.15,43.05 ; U29.7 52.83,20.95
  TOP w1.27: 58.24,30.73 58.24,32.02 58.17,32.1 TP6.1 58.17,42.04 57.15,43.05 L3.2
N1674311: length 12.7
  TOP w0.305: 43.47,41.16 L3.1 ; L3.1 41.93,43.05 ; L3.1 43.47,44.95 ; L3.1 45.02,43.05 ; 40.42,41.37 C94.2 ; C94.2 40.42,42.96 ; C94.2 41.19,42.16 ; 40.79,38.99 U28.9 40.36,40.01 ; U28.10 39.86,40.01 ; U28.11 39.36,40.01
N1674335: length 3.2
  TOP w0.203: C94.1 38.82,41.44 38.86,41.4 U28.12
N1674457: length 3.5
  TOP w0.203: R124.1 36.58,32.69 36.76,32.88 37.32,32.88 37.86,33.41 U28.3
N1674471: length 4.9
  TOP w0.203: C95.1 34.8,32.77 35.43,33.4 37.04,33.4 37.36,33.72 U28.2
N1674839: length 2.3
  TOP w0.203: U29.4 49.22,18.67 49.16,18.62 C103.1
N1674895: length 8
  TOP w0.203: U28.15 37.36,39.94 v1(37.06,40.24) ; C102.1 55.21,17.18 55.18,17.16 R125.2 52.96,17.16 52.75,17.37 52.75,19.6 52.4,19.95 U29.5
N1674997: length 4.6
  TOP w0.203: U28.4 38.36,32.53 38.35,32.52 R127.1 v1(39.28,31.93)
  BOTTOM w0.203: R127.1 v1(39.28,31.93)
N1676791: length 55.3
  TOP w0.203: 4.95,34.53 C106.2 ; U32.14 8.39,35.04 7.87,35.56 7.02,35.56 6.37,34.91
  TOP w0.305: C106.2 3.81,38.51 9.63,44.32 25.86,44.32 26.29,43.89 26.29,37.59
  TOP w1.27: 29.41,25.87 29.41,29.85 28.7,30.56 TP9.1 28.7,36.2 27.31,37.59 L4.2
N1677013: length 2.2
  TOP w0.203: 38.86,20.26 40,20.26 40.06,20.21 C117.1
N1677049: length 1.4
  TOP w0.203: v1(7.6,34.78) 7.89,34.48 U32.15
N1677171: length 4.6
  TOP w0.203: U32.4 8.9,27.07 8.89,27.06 R134.1 v1(9.82,26.47)
  BOTTOM w0.203: R134.1 v1(9.82,26.47)
N1677399: length 4.7
  TOP w0.203: R130.1 4.26,32.58 4.06,32.78 ; 6.15,32.65 7.11,32.65 7.39,32.94 U32.16 ; 4.06,32.78 C106.1 ; 4.06,32.78 4.83,32.78
N1677783: length 12.7
  TOP w0.305: L4.1 15.55,37.59 ; L4.1 14.01,39.49 ; L4.1 12.46,37.59 ; L4.1 14.01,35.7 ; C108.2 10.96,37.5 ; C108.2 11.73,36.7 ; C108.2 10.96,35.91 ; U32.10 10.39,34.55 ; 11.33,33.53 U32.9 10.89,34.55 ; U32.11 9.89,34.55
N1677807: length 3.2
  TOP w0.203: U32.12 9.39,35.94 9.36,35.97 C108.1
N1677819: length 4.8
  TOP w0.203: U32.13 8.9,35.55 8.26,36.2 v1(7.49,36.2) C107.1
N1677947: length 3.5
  TOP w0.203: U32.3 8.39,27.95 7.86,27.42 7.3,27.42 7.11,27.23 R131.1
N1677961: length 4.9
  TOP w0.203: C109.1 5.33,27.3 5.97,27.94 7.58,27.94 7.89,28.25 U32.2

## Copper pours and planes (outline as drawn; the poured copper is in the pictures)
3.3V on TOP (solid shape): 48.77,24.95 48.71,24.82 48.59,24.77 47.48,24.77 47.33,24.71 47.27,24.57 47.27,23.19 47.33,23.04 47.48,22.98 48.58,22.98 48.63,22.99 48.88,22.99 48.94,22.91 49.02,22.85 49.02,21.88 48.99,21.82 48.93,21.79 48.64,21.6 48.67,21.25 48.69,21.2 48.67,21.15 48.61,20.95 48.69,20.7 48.67,20.65 48.61,20.51 48.62,20.36 48.43,19.94 48.64,19.53 48.64,18.86 48.62,18.8 48.3,18.65 48.2,18.39 48.2,16.92 48.21,16.84 48.23,16.76 48.22,16.59 48.07,16.51 44.71,16.51 44.71,25.4 48.77,25.4
15V on TOP (solid shape): outline of 171 points within 9.3,17.78 14.86,28.36
15V on TOP (solid shape): 39.16,33.8 39.3,33.74 39.45,33.75 39.74,33.58 40.07,33.61 40.1,33.62 40.16,33.59 40.23,33.53 44.32,33.53 44.32,25.4 44.32,25.4 44.32,16.51 39.37,16.51 39.37,19.85 39.83,19.85 39.89,19.8 39.9,19.8 39.9,19.63 40.01,19.36 40.28,19.24 41.76,19.24 42.03,19.36 42.14,19.63 42.14,22.53 42.08,22.75 41.92,22.89 41.82,23 41.84,23.15 41.89,23.25 41.91,23.36 41.91,25.91 41.79,26.19 41.52,26.3 40.52,26.3 40.25,26.19 40.13,25.91 40.13,23.36 40.15,23.25 40.2,23.15 40.22,23 40.13,22.89 39.96,22.75 39.9,22.53 39.9,20.67 39.8,20.67 39.68,20.72 39.63,20.85 39.63,22.57 39.57,22.77 39.42,22.91 39.37,22.93 39.37,24.29 39.43,24.32 39.61,24.46 39.68,24.67 39.68,26.13 39.61,26.34 39.43,26.48 39.37,26.51 39.37,30.39 39.24,30.52 39.24,31.15 39.32,31.24 39.96,32.05 39.09,32.6 38.98,32.66 38.85,32.68 38.79,32.7 38.77,32.77 38.77,33.65 38.79,33.71 38.86,33.74 38.96,33.76 39.06,33.8 39.11,33.82
GND_SIGNAL on TOP (solid shape): 51.76,19.42 51.81,19.44 51.86,19.43 52.2,19.43 52.2,16.76 51.69,16.76 51.69,16.86 51.7,16.92 51.7,18.39 51.64,18.54 51.49,18.6 50.33,18.6 50.3,18.59 50.27,18.58 50.16,18.58 50.16,19.23 51.52,19.23 51.64,19.27 51.72,19.37
GND_SIGNAL on TOP (solid shape): 26.92,36.21 27.03,36.38 27.23,36.34 27.76,35.81 27.76,35.11 27.7,35.09 27.49,34.95 27.42,34.72 27.42,31.32 27.5,31.09 27.7,30.95 27.76,30.93 27.76,30.17 28.47,29.46 28.47,26.72 27.44,26.72 27.32,26.7 27.21,26.64 27.02,26.62 26.92,26.78
GND_SIGNAL on TOP (solid shape): outline of 178 points within 11.04,20.07 28.07,32.38
GND_SIGNAL on TOP (solid shape): outline of 261 points within 40.51,21.97 57.53,37.85
GND_SIGNAL on TOP (solid shape): outline of 93 points within 1.14,22.73 9.53,32.38
GND_SIGNAL on TOP (solid shape): outline of 107 points within 28.65,25.53 38.99,37.85
(no net) on TOP: 26.92,37.85 42.67,37.85 42.67,36.7 57.53,36.7 57.53,22.61 52.2,22.61 52.2,16.76 50.16,16.76 50.16,22.1 49.4,22.1 49.4,25.78 44.7,25.78 44.7,33.91 40.39,33.91 40.13,34.16 40.13,35.81 36.53,35.81 36.53,34.67 37.34,34.67 37.34,31.37 37.85,31.37 38.99,30.23 38.99,25.53 26.92,25.53
(no net) on TOP: 44.7,25.4 48.77,25.4 48.77,22.99 49.28,22.99 49.28,22 49.53,22 49.53,20.32 48.64,20.32 48.64,16.51 44.7,16.51
(no net) on TOP: 39.88,35.43 39.88,34.16 40.26,33.78 44.32,33.78 44.32,16.51 39.37,16.51 39.37,30.23 38.73,30.86 38.73,35.43
(no net) on TOP: 10.41,29.97 10.41,28.7 10.79,28.32 14.86,28.32 14.86,17.78 9.91,17.78 9.91,24.77 9.27,25.4 9.27,29.97
(no net) on TOP: 15.88,39.88 15.88,35.31 13.08,35.31 13.08,34.67 11.3,32.89 9.65,32.89 9.65,35.05 10.54,35.94 10.54,38.61 11.81,39.88
(no net) on TOP: 52.2,22.23 57.91,22.23 57.91,31.11 60.07,31.11 60.07,18.67 52.96,18.67 52.96,19.68 52.2,19.68
(no net) on TOP: 28.45,19.68 28.45,25.65 30.61,25.65 30.61,19.68
(no net) on TOP: 45.34,45.34 45.34,40.77 42.55,40.77 42.55,40.13 40.77,38.35 39.12,38.35 39.12,40.51 40.01,41.4 40.01,44.07 41.27,45.34
(no net) on TOP: 1.14,32.38 13.21,32.38 13.21,31.24 28.07,31.24 28.07,20.07 19.94,20.07 19.94,20.32 15.24,20.32 15.24,28.45 10.92,28.45 10.67,28.7 10.67,30.35 7.07,30.35 7.07,29.21 7.87,29.21 7.87,25.91 8.38,25.91 9.53,24.77 9.53,22.73 1.14,22.73
Net_86 on TOP (solid shape): 125.43,0.39 119.08,0.39 119.08,7.53 125.43,7.53
Net_87 on TOP (solid shape): 125.43,43.27 119.08,43.27 119.08,50.41 125.43,50.41
Net_88 on TOP (solid shape): 7.92,43.27 1.57,43.27 1.57,50.41 7.92,50.41
Net_89 on TOP (solid shape): 7.92,0.39 1.57,0.39 1.57,7.53 7.92,7.53
N1674071 on TOP (solid shape): 60.07,18.67 55.16,18.67 55.16,19.64 55.1,19.78 54.96,19.84 53.5,19.84 53.43,19.83 53.37,19.79 53.25,19.75 53.13,19.8 52.91,20.02 52.91,20.05 52.89,20.13 52.85,20.2 52.91,20.55 52.73,20.85 52.73,21.01 52.67,21.15 52.66,21.2 52.67,21.25 52.73,21.51 52.58,21.74 52.58,22.22 53.53,22.22 53.57,22.2 53.62,22.13 53.59,22.05 53.54,21.98 53.52,21.9 53.52,20.95 53.58,20.8 53.73,20.74 54.73,20.74 54.87,20.8 54.94,20.95 54.94,21.9 54.92,21.98 54.87,22.05 54.84,22.13 54.89,22.2 54.93,22.22 55.19,22.22 55.31,22.17 55.36,22.04 55.36,20.93 55.43,20.79 55.57,20.73 56.95,20.73 57.1,20.79 57.16,20.93 57.16,22.04 57.21,22.17 57.33,22.22 57.91,22.22 57.91,31.11 60.07,31.11
N1674311 on TOP (solid shape): outline of 127 points within 39.27,38.54 45.34,45.34
N1676791 on TOP (solid shape): 30.61,19.68 28.45,19.68 28.45,25.65 30.61,25.65
N1677783 on TOP (solid shape): outline of 127 points within 9.8,33.08 15.88,39.88

Small or netless copper shapes (teardrops, artwork), in the pictures only: 4 on TOP

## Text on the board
User.Comments: CR_P3_5 | CR_P1_3 | CR_P1_4 | CR_PS_1
Ref Des/Silkscreen Top: CAN | RS485 | DIFFP | ENCDR | PWM | VI/MN | PSIGB | LOAD | LRF | PWR | EMC | DIGIO | RS232 | ICD | 10021168rA | PB BOOST | CONTROLLER
XSECTION_CHART: L1: TOP CONDUCTOR - COPPER 1.4 MIL | *  DIELECTRIC - FR-4 5.1 MIL | *  DIELECTRIC - FR-4 4.7 MIL | L2: GND1 CONDUCTOR - COPPER 1.4 MIL | *  DIELECTRIC - FR-4 14 MIL | L3: PWR CONDUCTOR - COPPER 1.4 MIL | *  DIELECTRIC - FR-4 4.2 MIL | L4: INR1 CONDUCTOR - COPPER 1.4 MIL | L5: GND2 CONDUCTOR - COPPER 1.4 MIL | L6: BOTTOM CONDUCTOR - COPPER 1.4 MIL | DESIGN CROSS SECTION CHART | ___________________________ | TOTAL THICKNESS 64.4 MIL | 1-6
PLACE_BOUND_BOTTOM: FIGURE | SIZE | 10.0 | 32.0 | 38.0 | 40.0 | 44.0 | 126.0 | DRILL CHART: TOP to BOTTOM | ALL UNITS ARE IN MILS | PLATED | QTY | 366 | 72 | 56 | 4 | 2
